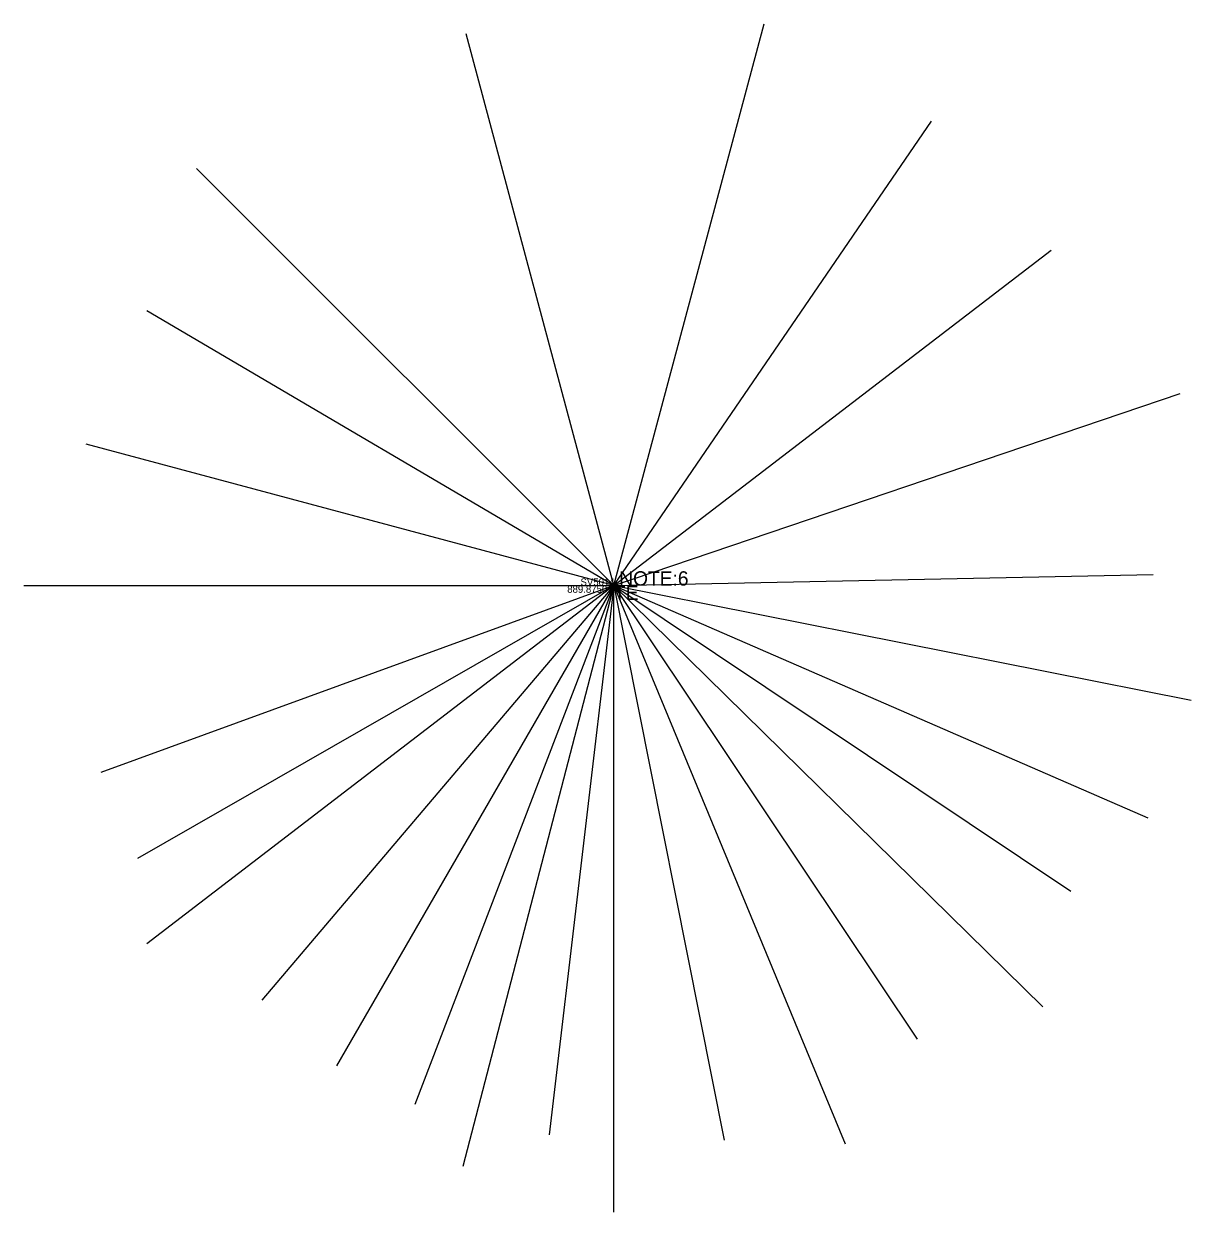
# Model space of a CAD drawing. Extents: x 179577 to 181071, y 300448 to 300709.
# Drawn here: x 179647.77 to 179657.53, y 300631.25 to 300641.18 of the extents above; entities that cross this region are included whole.
import ezdxf

# ---------------------------------------------------------------- set-up
doc = ezdxf.new("R2010")
doc.units = 0
for name, color, linetype in [('SV_X_Text_Comment', 7, 'Continuous'), ('SV_X_Text_Elevation', 7, 'Continuous'), ('SV_X_Text_Name', 7, 'Continuous'), ('VG_X_Cells', 7, 'Continuous'), ('VG_X_Text', 7, 'Continuous')]:
    doc.layers.add(name, color=color, linetype=linetype)

msp = doc.modelspace()

# ---------------------------------------------------------------- linework, layer by layer
at = {"layer": 'VG_X_Cells'}
for p, q in [((179652.7054, 300636.4866), (179653.9621, 300641.1849)), ((179652.7054, 300636.4866), (179651.4704, 300641.0999)), ((179652.7054, 300636.4866), (179655.3604, 300640.3716)), ((179652.7054, 300636.4866), (179649.2154, 300639.9733)), ((179652.7054, 300636.4866), (179656.3621, 300639.2916)), ((179652.7054, 300636.4866), (179648.7987, 300638.7833)), ((179652.7054, 300636.4866), (179657.4421, 300638.0933)), ((179652.7054, 300636.4866), (179648.2921, 300637.6699)), ((179652.7054, 300636.4866), (179657.2154, 300636.5783)), ((179647.7704, 300636.4866), (179652.7054, 300636.4866)), ((179652.7054, 300636.4866), (179648.4154, 300634.9249)), ((179652.7054, 300636.4866), (179648.7221, 300634.2049)), ((179652.7054, 300636.4866), (179648.7987, 300633.4916)), ((179652.7054, 300636.4866), (179649.7604, 300633.0199)), ((179652.7054, 300636.4866), (179650.3871, 300632.4716)), ((179652.7054, 300636.4866), (179651.0404, 300632.1466)), ((179652.7054, 300636.4866), (179651.4421, 300631.6299)), ((179652.7054, 300636.4866), (179652.1637, 300631.8949)), ((179652.7054, 300631.2466), (179652.7054, 300636.4866)), ((179652.7054, 300636.4866), (179653.6271, 300631.8499)), ((179652.7054, 300636.4866), (179654.6387, 300631.8183)), ((179652.7054, 300636.4866), (179655.2421, 300632.6933)), ((179652.7054, 300636.4866), (179656.2937, 300632.9649)), ((179652.7054, 300636.4866), (179656.5271, 300633.9316)), ((179652.7054, 300636.4866), (179657.1704, 300634.5449)), ((179652.7054, 300636.4866), (179657.5337, 300635.5283))]:
    msp.add_line(p, q, dxfattribs=at)

# ---------------------------------------------------------------- texts
at = {"layer": 'SV_X_Text_Comment'}
msp.add_text('TE', height=0.12, dxfattribs=at).set_placement((179652.7054, 300636.3666))
at = {"layer": 'SV_X_Text_Elevation'}
msp.add_text('889.8750', height=0.06, dxfattribs=at).set_placement((179652.3152, 300636.4266))
at = {"layer": 'SV_X_Text_Name'}
msp.add_text('SV5014', height=0.06, dxfattribs=at).set_placement((179652.4262, 300636.4866))
at = {"layer": 'VG_X_Text'}
msp.add_text(' NOTE:6', height=0.12, dxfattribs=at).set_placement((179652.7054, 300636.4866))

doc.saveas('drawing.dxf')
